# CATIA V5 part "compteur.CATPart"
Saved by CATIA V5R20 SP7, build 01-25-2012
Part number: compteur
Bounding box of the stored display mesh (mm): x 32.31 to 48.31, y -84 to -60, z 8.01 to 31.99
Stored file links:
  F:\Travaux\Modélisations\CFAO_2011\CFAO_2011_MMS\CFAO_2011_MMS_DONE\CFAO_2011_MMS_jboiteux\Catia\compteur.CATPart
  U:\finthinkmotion\stepper.CATProduct
  F:\Travaux\Modélisations\CFAO_2011\CFAO_2011_MMS\CFAO_2011_MMS_DONE\CFAO_2011_MMS_jboiteux\Catia\Part1.CATPart
  F:\Travaux\Modélisations\CFAO_2011\CFAO_2011_MMS\CFAO_2011_MMS_DONE\CFAO_2011_MMS_jboiteux\Catia\bati.CATPart
  F:\Travaux\Modélisations\CFAO_2011\CFAO_2011_MMS\CFAO_2011_MMS_DONE\CFAO_2011_MMS_jboiteux\Catia\Roulement plastique.CATPart
  F:\Travaux\Modélisations\CFAO_2011\CFAO_2011_MMS\CFAO_2011_MMS_DONE\CFAO_2011_MMS_jboiteux\Catia\Part2.CATPart
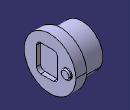
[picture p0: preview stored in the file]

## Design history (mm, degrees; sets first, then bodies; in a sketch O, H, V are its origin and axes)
Parameters
  rayontube = 9 mm {= External.royontubebati}
External parameters (linked from other documents)
  External.royontubebati = 9 mm
Set1
  Plane1: linked copy from another document
  DatumSurface1: linked copy from another document
  Point1: linked copy from another document
  DatumCurve1: linked copy from another document
  Line1: linked copy from another document
  Line2: linked copy from another document
Body1 (main body)
  Sketch1 on Plane1, origin (42.31, 0, 0), H (0, 1, 0), V (0, 0, 1)
    projected circle E1 centre (-72, 20) radius 9.6 from face of DatumSurface1
    circle A1 centre (-72, 20) radius 8
    point P1 (-72, 20)
    reference projected point E2 (-72, 20) from Point1
    radius A1 = 8 {= rayontube *4/3-4 mm}
    coincidence: E2 P1
  Pad1: profile Sketch1, direction (-1, 0, 0), length 10
  Sketch2 on Plane1, origin (42.31, 0, 0), H (0, 1, 0), V (0, 0, 1)
    projected circle E1 centre (-72, 20) radius 12 from edge of DatumCurve1
  Pad2: profile Sketch2, direction (1, 0, 0), length 5
  Sketch3 on Plane1, origin (42.31, 0, 0), H (0, 1, 0), V (0, 0, 1)
    line L1 (-78.3, 13.7) -> (-68.4, 13.7)
    line L2 (-68.4, 13.7) -> (-68.4, 26.3)
    line L3 (-68.4, 26.3) -> (-78.3, 26.3)
    line L4 (-78.3, 26.3) -> (-78.3, 13.7)
    reference projected line E1 (-96, 20) -> (-36, 20) from Line2
    reference projected line E2 (-96, 20) -> (-36, 20) from Line2
    circle A1 centre (-63.9, 20) radius 2.25
    point P5 (-63.9, 20)
    reference projected line E3 (-96, 20) -> (-36, 20) from Line2
    reference projected point E4 (-72, 20) from Point1
    distance L3 E1 = 6.3 {= rayontube *0.7}
    distance L1 E2 = 6.3 {= rayontube *0.7}
    radius A1 = 2.25 {= rayontube /4}
    distance P5 E3 = 0
    distance P5 E4 = 8.1 {= rayontube*0.9}
    distance L2 L4 = 9.9 {= rayontube *1.1}
    angle L4 L3 = 90
    distance L2 P5 = 4.5 {= rayontube *0.5}
    horizontal: L1 H, L3 H
  Sketch4 on end face of Pad2, origin (47.31, 0, 0), H (0, 1, 0), V (0, 0, 1)
    projected line E1 (-68.4, 26.3) -> (-78.3, 26.3) from Sketch3.L3
    projected line E2 (-68.4, 13.7) -> (-68.4, 26.3) from Sketch3.L2
    projected line E3 (-78.3, 13.7) -> (-68.4, 13.7) from Sketch3.L1
    projected line E4 (-78.3, 26.3) -> (-78.3, 13.7) from Sketch3.L4
  Pocket1: profile Sketch4, direction (-1, 0, 0), length 2
  Fillet1: radius 2 {= rayontube /4.5}, on edge [face of Pocket1 from Sketch4.E4 | face of Pocket1 from Sketch4.E1]; edge [face of Pocket1 from Sketch4.E1 | face of Pocket1 from Sketch4.E2]; edge [face of Pocket1 from Sketch4.E3 | face of Pocket1 from Sketch4.E4]; edge [face of Pocket1 from Sketch4.E2 | face of Pocket1 from Sketch4.E3]
  Sketch5 on end face of Pad2, origin (47.31, 0, 0), H (0, 1, 0), V (0, 0, 1)
    projected circle E1 centre (-63.9, 20) radius 2.25 from Sketch3.A1
  Pad3: profile Sketch5, direction (1, 0, 0), length 1
  Fillet2: radius 0.5 {= rayontube /18}, on end face of Pad3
